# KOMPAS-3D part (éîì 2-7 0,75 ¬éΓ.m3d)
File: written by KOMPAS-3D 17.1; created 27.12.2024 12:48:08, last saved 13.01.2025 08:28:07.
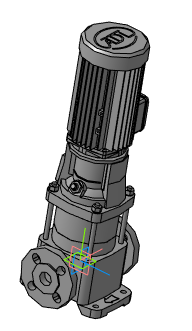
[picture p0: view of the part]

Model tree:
1. Операция без истории:4  (labels: ВМН 2-7 0,75 кВт)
